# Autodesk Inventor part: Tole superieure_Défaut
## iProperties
Shininess: 64.0
Length Units: 11269
Angle Units: 11279
Time Units: 11290
Mass Units: 11283
Length Display Precision: 3
Angle Display Precision: 2
Compacted: True
Part Number: Tole superieure_Défaut
Document SubType Name: Modeling
Created: 2006-01
Material: Par défaut
Designer: Fricot
Density: 0.0
Volumn: 0.0
Area: 0.0
PropertySet Name: Model Information
Control State: 0
Master: False
Checked Out: False
Author: Fricot
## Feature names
1. Base1
